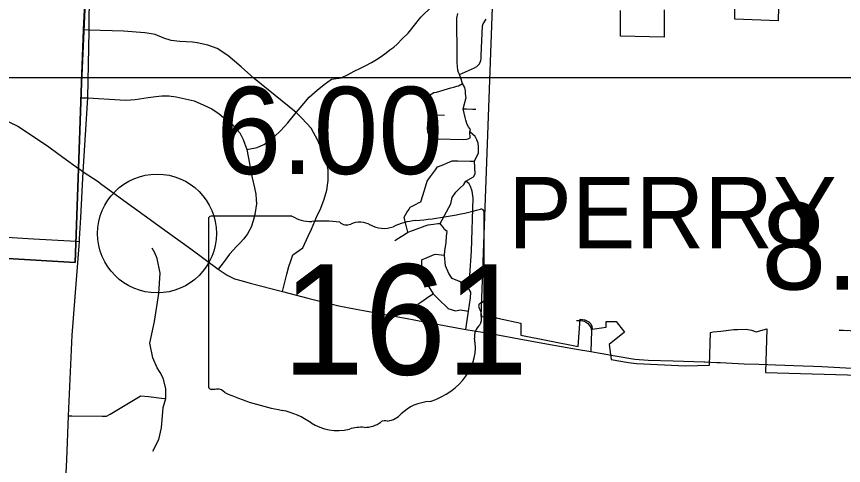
# Model space of a CAD drawing. Extents: x 1659811 to 1934326, y 644115 to 934867.
# Drawn here: x 1802180 to 1812622, y 760605 to 766269 of the extents above; entities that cross this region are included whole.
import ezdxf

# ---------------------------------------------------------------- set-up
doc = ezdxf.new("R2010")
doc.units = 0
for name, color, linetype in [('Default', 7, 'Continuous'), ('GM_X_City_Street', 7, 'Continuous'), ('GM_X_Corporation', 7, 'Continuous'), ('GM_X_State_Route', 7, 'Continuous'), ('GM_X_State_Shield', 7, 'Continuous'), ('GM_X_Township', 7, 'Continuous'), ('GM_X_Township_Text', 7, 'Continuous'), ('SC_Scratch1', 7, 'Continuous')]:
    doc.layers.add(name, color=color, linetype=linetype)

msp = doc.modelspace()

# ---------------------------------------------------------------- linework, layer by layer
at = {"layer": 'Default'}
msp.add_circle((1803954, 763532), 750, dxfattribs=at)
at = {"layer": 'GM_X_City_Street'}
for points in [[(1803099, 766088), (1803099, 766099), (1803106, 767083), (1803132, 767474), (1803133, 767507)], [(1805742, 765094), (1805876, 765250), (1805975, 765341), (1806064, 765411), (1806159, 765477), (1806278, 765497), (1806366, 765539), (1806444, 765578), (1806514, 765615), (1806589, 765653), (1806663, 765690), (1806725, 765726), (1806783, 765767), (1806846, 765810), (1806895, 765849), (1806943, 765883), (1806988, 765920), (1807051, 765987), (1807127, 766061), (1807287, 766261), (1807423, 766398), (1807582, 766554), (1807747, 766689), (1807795, 766714)], [(1807530, 763658), (1807662, 763908), (1807680, 763986), (1807726, 764055), (1807775, 764101), (1807827, 764150), (1807855, 764194), (1807951, 764245), (1807971, 764283), (1807962, 764444), (1808012, 764551), (1808014, 764625), (1808008, 764671), (1807994, 764712), (1807972, 764757), (1807906, 764815), (1807912, 764842), (1807887, 764877), (1807870, 764907), (1807853, 764961), (1807844, 764995), (1807819, 765103), (1807857, 765249), (1807851, 765293), (1807848, 765333), (1807839, 765373), (1807811, 765423), (1807791, 765491), (1807772, 765538), (1807763, 765562), (1807752, 765592), (1807747, 765633), (1807742, 765692), (1807744, 765775), (1807741, 766249), (1807752, 766309)], [(1807772, 765538), (1807965, 765622), (1807994, 765641), (1808011, 765657), (1808025, 765674), (1808035, 765693), (1808043, 765714), (1808049, 765739), (1808049, 765777), (1808064, 766154), (1808073, 766177), (1808110, 766237)], [(1803022, 764311), (1803078, 765243), (1803099, 766088)], [(1803829, 766059), (1803801, 766063), (1803529, 766085), (1803099, 766099), (1803026, 766103)], [(1805537, 762802), (1805591, 763017), (1805619, 763116), (1805642, 763189), (1805668, 763261), (1805795, 763353), (1805863, 763498), (1805903, 763585), (1805969, 763738), (1806022, 763853), (1806065, 763965), (1806097, 764077), (1806117, 764201), (1806113, 764335), (1806086, 764473), (1805984, 764704), (1805899, 764861), (1805783, 764988), (1805711, 765058), (1805180, 765489), (1805015, 765635), (1804848, 765777), (1804714, 765864), (1804594, 765908), (1804460, 765938), (1804401, 765946), (1804241, 765953), (1804131, 765969), (1804040, 765996), (1803932, 766042), (1803829, 766059)], [(1807395, 764764), (1807381, 764789), (1807372, 764815), (1807371, 764856), (1807380, 765035), (1807387, 765201), (1807391, 765242), (1807399, 765269), (1807410, 765285), (1807430, 765300), (1807450, 765309), (1807481, 765317), (1807664, 765370), (1807704, 765379), (1807738, 765389), (1807760, 765397), (1807811, 765423)], [(1802995, 765243), (1803078, 765243), (1803488, 765219)], [(1803488, 765219), (1803560, 765215), (1803676, 765222), (1803841, 765246), (1803937, 765262), (1804016, 765268), (1804103, 765267), (1804195, 765256), (1804309, 765231), (1804423, 765204), (1804546, 765153), (1804647, 765103), (1804739, 765041), (1804824, 764970), (1804898, 764914), (1804998, 764802), (1805043, 764719), (1805088, 764592), (1805120, 764417), (1805140, 764308), (1805154, 764234), (1805186, 764109), (1805203, 764030), (1805206, 763961), (1805208, 763904), (1805191, 763772), (1805169, 763691), (1805143, 763613), (1805096, 763527), (1805050, 763463), (1805001, 763411), (1804967, 763378)], [(1805088, 764592), (1805218, 764618), (1805301, 764653), (1805351, 764686), (1805440, 764759), (1805514, 764829), (1805604, 764929), (1805711, 765058), (1805742, 765094)], [(1807380, 765035), (1807585, 765025)], [(1807819, 765103), (1807860, 765103), (1807941, 765101), (1807981, 765100)], [(1807395, 764764), (1807425, 764742), (1807454, 764730), (1807491, 764728), (1807824, 764717), (1807860, 764720), (1807882, 764725), (1807908, 764737), (1807906, 764815)], [(1807122, 763547), (1807110, 763598), (1807085, 763700), (1807076, 763738), (1807109, 763795), (1807136, 763840), (1807149, 763863), (1807219, 763898), (1807266, 763922), (1807284, 763931), (1807309, 764012), (1807356, 764162), (1807365, 764190), (1807409, 764252), (1807471, 764337), (1807495, 764371), (1807553, 764395), (1807650, 764437), (1807679, 764449), (1807752, 764448), (1807909, 764445), (1807962, 764444)], [(1802975, 763466), (1802992, 763735), (1803022, 764311)], [(1807851, 762878), (1807896, 762947), (1807906, 763002), (1807925, 763311), (1807945, 763978), (1807935, 764065), (1807911, 764126), (1807894, 764160), (1807855, 764194)], [(1798361, 763811), (1798627, 763794), (1798910, 763775), (1799187, 763750), (1799393, 763707), (1799473, 763682), (1799519, 763619), (1799605, 763594), (1799681, 763585), (1800138, 763556), (1800142, 763555), (1800675, 763521), (1801008, 763551), (1801581, 763516), (1802396, 763466), (1802931, 763434), (1802973, 763432)], [(1806957, 763442), (1807003, 763471), (1807093, 763529), (1807122, 763547), (1807191, 763573), (1807342, 763628), (1807379, 763642), (1807447, 763651), (1807500, 763658), (1807530, 763658)], [(1807854, 762876), (1807851, 762878), (1807772, 762926), (1807682, 762966), (1807637, 763027), (1807596, 763125), (1807583, 763257), (1807590, 763315), (1807605, 763419), (1807610, 763499), (1807619, 763559), (1807586, 763582), (1807569, 763611), (1807548, 763635), (1807530, 763658)], [(1802583, 755808), (1802702, 758234), (1802783, 760019), (1802813, 760675), (1802837, 761232), (1802881, 762249), (1802973, 763432), (1802975, 763466)], [(1803902, 760785), (1803975, 760933), (1804012, 761080), (1804031, 761338), (1804066, 761449), (1804067, 761577), (1804031, 761706), (1803994, 761779), (1803957, 761835), (1803902, 761963), (1803865, 762147), (1803920, 762423), (1803975, 762773), (1803994, 763031), (1803957, 763215), (1803928, 763286), (1803891, 763347)], [(1804967, 763378), (1804954, 763365), (1804918, 763325), (1804869, 763271), (1804813, 763194), (1804776, 763146), (1804726, 763080)], [(1807294, 763201), (1807334, 763217), (1807455, 763267), (1807470, 763273), (1807540, 763263), (1807583, 763257)], [(1807294, 763201), (1807294, 763149), (1807294, 763097), (1807294, 763095), (1807322, 762997), (1807336, 762948), (1807342, 762928), (1807386, 762858), (1807440, 762771), (1807514, 762698), (1807626, 762590), (1807628, 762587), (1807724, 762557), (1807788, 762568), (1807888, 762550)], [(1807853, 762322), (1807888, 762550), (1807914, 762718), (1807917, 762792), (1807888, 762842), (1807854, 762876)], [(1807246, 762639), (1807285, 762666), (1807401, 762745), (1807440, 762771)], [(1808210, 762262), (1808221, 762468)], [(1809252, 762433), (1809254, 762434), (1809310, 762436), (1809350, 762427), (1809392, 762401), (1809416, 762373), (1809430, 762347), (1809441, 762303), (1809431, 762042)], [(1802837, 761232), (1802878, 761231), (1803262, 761225), (1803314, 761225), (1803363, 761254), (1803740, 761479), (1803751, 761485), (1803848, 761474), (1804011, 761455), (1804066, 761449)]]:
    msp.add_lwpolyline(points, dxfattribs=at)
at = {"layer": 'GM_X_Corporation'}
for points in [[(1799794, 779878), (1803634, 779704), (1803603, 778383), (1803585, 777445), (1803558, 776945), (1803483, 775420), (1803430, 774349), (1803319, 771942), (1803249, 770602), (1803163, 769065), (1803153, 768757), (1803149, 768674), (1803140, 768585), (1803123, 768218), (1803091, 767476), (1803002, 765433), (1802964, 764353), (1802922, 763165), (1799354, 763375)], [(1799794, 779878), (1803634, 779704), (1803603, 778383), (1803585, 777445), (1803558, 776945), (1803483, 775420), (1803430, 774349), (1803319, 771942), (1803249, 770602), (1803163, 769065), (1803153, 768757), (1803149, 768674), (1803140, 768585), (1803123, 768218), (1803091, 767476), (1803002, 765433), (1802964, 764353), (1802922, 763165), (1799354, 763375)], [(1799354, 763375), (1802922, 763165), (1802964, 764353), (1803002, 765433), (1803091, 767476), (1803123, 768218), (1803140, 768585), (1803149, 768674), (1803153, 768757), (1803163, 769065), (1803249, 770602), (1803319, 771942), (1803430, 774349)], [(1811812, 766729), (1811796, 766216), (1811252, 766235), (1811245, 766768)], [(1808185, 766383), (1808045, 762485), (1808195, 762479), (1808275, 762459), (1808546, 762402), (1808548, 762250), (1809272, 762106), (1809298, 762449), (1809355, 762441), (1809405, 762419), (1809431, 762391), (1809443, 762364), (1809447, 762323), (1809626, 762351), (1809624, 762423), (1809754, 762422), (1809856, 762286), (1809663, 762131), (1809689, 761942), (1809909, 761903), (1810009, 761892), (1810629, 761862), (1810931, 761869), (1810942, 762284), (1810976, 762290), (1811074, 762298), (1811239, 762322), (1811286, 762320), (1811393, 762324), (1811462, 762312), (1811518, 762292), (1811655, 762328), (1811639, 761776), (1812969, 761741)], [(1810359, 766356), (1810358, 766008), (1809808, 766020), (1809808, 766345)], [(1812678, 762305), (1812570, 762310), (1812577, 762312), (1812587, 762314), (1812598, 762314), (1812612, 762314), (1812803, 762305)]]:
    msp.add_lwpolyline(points, dxfattribs=at)
at = {"layer": 'GM_X_State_Route'}
for points in [[(1798670, 765290), (1799362, 765240), (1800021, 765204), (1800851, 765152), (1801408, 765122), (1801560, 765103), (1801728, 765068), (1801876, 765025), (1801994, 764982), (1802098, 764934), (1802195, 764884), (1802305, 764816), (1802588, 764624), (1802766, 764496)], [(1802766, 764496), (1802964, 764353), (1802979, 764342)], [(1802979, 764342), (1803022, 764311), (1803210, 764186), (1803242, 764163)], [(1803242, 764163), (1803628, 763881), (1803670, 763850)], [(1803670, 763850), (1804081, 763552), (1804379, 763337), (1804726, 763080), (1804838, 763008), (1804883, 762984), (1804933, 762961), (1805027, 762933), (1805129, 762904), (1805537, 762802), (1805540, 762801)], [(1805540, 762801), (1805859, 762717), (1806251, 762620), (1806469, 762576), (1806560, 762559), (1806996, 762480), (1807093, 762462)], [(1807093, 762462), (1807353, 762412), (1807853, 762322), (1808063, 762288), (1808137, 762275)], [(1808137, 762275), (1808210, 762262), (1808525, 762203), (1808874, 762141), (1809249, 762074), (1809431, 762042), (1809525, 762027), (1809599, 762014)], [(1809599, 762014), (1809714, 761993), (1809986, 761945), (1810158, 761935), (1810473, 761924), (1810864, 761911)], [(1810864, 761911), (1810871, 761911), (1811023, 761905)], [(1811023, 761905), (1811065, 761903), (1811370, 761888), (1811553, 761881)], [(1811553, 761881), (1811667, 761877), (1811765, 761874)], [(1811765, 761874), (1812112, 761862), (1812242, 761857), (1812348, 761852)], [(1812348, 761852), (1812729, 761834), (1812989, 761827)]]:
    msp.add_lwpolyline(points, dxfattribs=at)
at = {"layer": 'GM_X_State_Shield'}
for p, q in [((1808084, 762699), (1808084, 763804)), ((1804604, 763715), (1804604, 761602)), ((1805657, 763752), (1804638, 763752)), ((1808084, 762699), (1808084, 762699))]:
    msp.add_line(p, q, dxfattribs=at)
for centre, major_axis, start_param, end_param in [((1806844, 766633), (3691, 0), 4.814394, 5.042369), ((1808045, 763809), (38.7, 0), 6.141152, 7.989035), ((1804643, 763720), (40.3, 0), 1.712693, 3.28349), ((1805900, 763997), (391, 0), 4.042523, 4.731795), ((1806029, 762565), (1404, 0), 1.404758, 1.657858), ((1806348, 763731), (113, 0), 3.836095, 5.185415), ((1806514, 763486), (235, 0), 0.950623, 2.079405), ((1807315, 763106), (743, 0), 1.699011, 2.107814), ((1806817, 763822), (282, 0), 4.081561, 5.145723), ((1808075, 762617), (60, 0), 1.883978, 3.671073), ((1808043, 762694), (41.5, 0), 5.05454, 6.418171), ((1807694, 762478), (360, 0), 5.934695, 6.695948), ((1808223, 762236), (262, 0), 2.387724, 3.262537), ((1807051, 762095), (923, 0), 5.101752, 6.440018), ((1804644, 761597), (40.7, 0), 3.00124, 4.508301), ((1804713, 761480), (112, 0), 0.519207, 1.627899), ((1804650, 761814), (310, 0), 4.665946, 4.897461), ((1806127, 763379), (2665, 0), 4.195997, 4.488961), ((1807440, 761009), (506, 0), 1.647645, 2.488434), ((1805332, 760653), (834, 0), 0.823519, 1.323587), ((1806578, 761311), (282, 0), 4.691044, 5.507374), ((1806833, 761107), (79.4, 0), 1.147584, 2.315152), ((1806800, 761397), (298, 0), 4.937069, 5.64225), ((1806234, 761470), (529, 0), 4.026481, 4.996735), ((1806540, 760739), (435, 0), 1.495662, 1.94098)]:
    msp.add_ellipse(centre, major_axis=major_axis, ratio=0.8, start_param=start_param, end_param=end_param, dxfattribs=at)
at = {"layer": 'GM_X_Township'}
msp.add_lwpolyline([(1799354, 763375), (1802922, 763165), (1802931, 763434), (1802964, 764353), (1802995, 765243), (1803002, 765433), (1803026, 766103), (1803091, 767476), (1803123, 768218), (1803140, 768585), (1803149, 768674), (1803153, 768757), (1803163, 769065), (1803249, 770602), (1803319, 771948), (1803379, 773502), (1803430, 774349), (1803455, 774923), (1803472, 775394), (1803558, 776945), (1803585, 777445), (1803603, 778383), (1803634, 779704), (1803704, 779701)], dxfattribs=at)
at = {"layer": 'SC_Scratch1'}
msp.add_lwpolyline([(1729596, 899996), (1925846, 899996), (1925846, 765496), (1729596, 765496)], close=True, dxfattribs=at)

# ---------------------------------------------------------------- texts
at = {"layer": 'Default'}
for s, p in [('6.00', (1804704, 764282)), ('8.00', (1811586, 762825))]:
    msp.add_text(s, height=1100, dxfattribs=at).set_placement(p)
at = {"layer": 'GM_X_State_Shield'}
msp.add_text('161', height=1392.2, dxfattribs=at).set_placement((1805534, 761751))
at = {"layer": 'GM_X_Township_Text'}
msp.add_text('PERRY', height=900, rotation=0, dxfattribs=at).set_placement((1808390, 763345))

doc.saveas('drawing.dxf')
